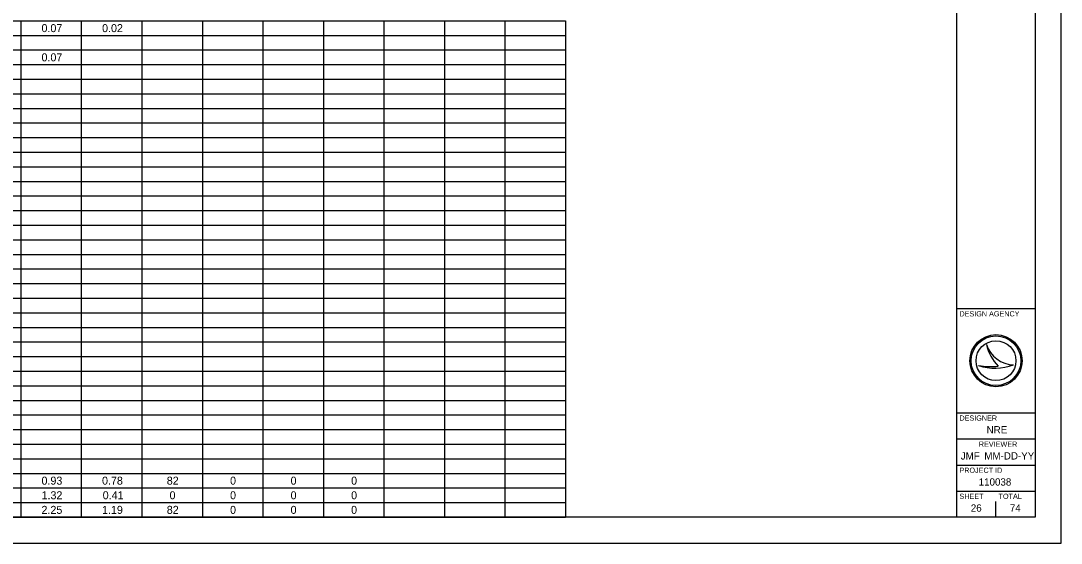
# Model space of a CAD drawing. Extents: x 0 to 34, y 0 to 22.
# Drawn here: x 14.06 to 34, y 0 to 10.02 of the extents above; entities that cross this region are included whole.
import ezdxf

# ---------------------------------------------------------------- set-up
doc = ezdxf.new("R2010")
doc.units = 0
for name, color, linetype in [('SH_Border', 7, 'Continuous'), ('SH_Cut_Line', 7, 'Continuous'), ('SH_Data', 7, 'Continuous'), ('SH_Text', 7, 'Continuous')]:
    doc.layers.add(name, color=color, linetype=linetype)

msp = doc.modelspace()

# ---------------------------------------------------------------- linework, layer by layer
at = {"layer": 'SH_Border'}
for p, q in [((32, 0.5), (32, 21.5)), ((32, 4.5), (33.5, 4.5)), ((32, 2.5), (33.5, 2.5)), ((32, 2), (33.5, 2)), ((32, 1.5), (33.5, 1.5)), ((32, 1), (33.5, 1))]:
    msp.add_line(p, q, dxfattribs=at)
msp.add_lwpolyline([(1.5, 21.5), (33.5, 21.5), (33.5, 0.5), (1.5, 0.5)], close=True, dxfattribs=at)
at = {"layer": 'SH_Cut_Line'}
msp.add_lwpolyline([(0, 0), (34, 0), (34, 22), (0, 22)], close=True, dxfattribs=at)
at = {"layer": 'SH_Data'}
for p, q in [((32.567, 3.81), (32.567, 3.81)), ((32.417, 3.41), (32.417, 3.41)), ((32.75, 3.5), (32.75, 3.5)), ((33.087, 3.419), (33.087, 3.419)), ((32.75, 0.5), (32.75, 0.8)), ((32.375, 0.675), (32.375, 0.675))]:
    msp.add_line(p, q, dxfattribs=at)
for radius in [0.5, 0.477, 0.477, 0.382]:
    msp.add_circle((32.75, 3.5), radius, dxfattribs=at)
for centre, radius, start, end in [((33.116, 3.998), 0.58, 198.9257, 198.9319), ((33.347, 3.97), 0.796, 191.6379, 191.6421), ((33.116, 3.998), 0.58, 198.9319, 267.1657), ((33.347, 3.97), 0.796, 191.6421, 226.0947), ((32.739, 4.37), 1.013, 251.4576, 290.0832), ((32.648, 4.654), 1.266, 259.4964, 259.4995), ((32.739, 4.37), 1.013, 251.4527, 251.4576), ((32.648, 4.654), 1.266, 259.4995, 276.6672)]:
    msp.add_arc(centre, radius, start, end, dxfattribs=at)
at = {"layer": 'SH_Text'}
for p, q in [((3.02, 10.02), (14.06, 10.02)), ((14.06, 10.02), (16.38, 10.02)), ((14.06, 10.02), (14.06, 9.74)), ((15.22, 10.02), (15.22, 9.74)), ((16.38, 10.02), (21.02, 10.02)), ((16.38, 10.02), (16.38, 9.74)), ((17.54, 10.02), (17.54, 9.74)), ((18.7, 10.02), (18.7, 9.74)), ((19.86, 10.02), (19.86, 9.74)), ((21.02, 10.02), (23.34, 10.02)), ((21.02, 10.02), (21.02, 9.74)), ((22.18, 10.02), (22.18, 9.74)), ((23.34, 10.02), (24.5, 10.02)), ((23.34, 10.02), (23.34, 9.74)), ((24.5, 10.02), (24.5, 9.74)), ((3.02, 9.74), (14.06, 9.74)), ((14.06, 9.74), (16.38, 9.74)), ((14.06, 9.74), (14.06, 9.46)), ((15.22, 9.74), (15.22, 9.46)), ((16.38, 9.74), (21.02, 9.74)), ((16.38, 9.74), (16.38, 9.46)), ((17.54, 9.74), (17.54, 9.46)), ((18.7, 9.74), (18.7, 9.46)), ((19.86, 9.74), (19.86, 9.46)), ((21.02, 9.74), (23.34, 9.74)), ((21.02, 9.74), (21.02, 9.46)), ((22.18, 9.74), (22.18, 9.46)), ((23.34, 9.74), (24.5, 9.74)), ((23.34, 9.74), (23.34, 9.46)), ((24.5, 9.74), (24.5, 9.46)), ((3.02, 9.46), (14.06, 9.46)), ((14.06, 9.46), (16.38, 9.46)), ((14.06, 9.46), (14.06, 9.18)), ((15.22, 9.46), (15.22, 9.18)), ((16.38, 9.46), (21.02, 9.46)), ((16.38, 9.46), (16.38, 9.18)), ((17.54, 9.46), (17.54, 9.18)), ((18.7, 9.46), (18.7, 9.18)), ((19.86, 9.46), (19.86, 9.18)), ((21.02, 9.46), (23.34, 9.46)), ((21.02, 9.46), (21.02, 9.18)), ((22.18, 9.46), (22.18, 9.18)), ((23.34, 9.46), (24.5, 9.46)), ((23.34, 9.46), (23.34, 9.18)), ((24.5, 9.46), (24.5, 9.18)), ((3.02, 9.18), (14.06, 9.18)), ((14.06, 9.18), (16.38, 9.18)), ((14.06, 9.18), (14.06, 8.9)), ((15.22, 9.18), (15.22, 8.9)), ((16.38, 9.18), (21.02, 9.18)), ((16.38, 9.18), (16.38, 8.9)), ((17.54, 9.18), (17.54, 8.9)), ((18.7, 9.18), (18.7, 8.9)), ((19.86, 9.18), (19.86, 8.9)), ((21.02, 9.18), (23.34, 9.18)), ((21.02, 9.18), (21.02, 8.9)), ((22.18, 9.18), (22.18, 8.9)), ((23.34, 9.18), (24.5, 9.18)), ((23.34, 9.18), (23.34, 8.9)), ((24.5, 9.18), (24.5, 8.9)), ((3.02, 8.9), (14.06, 8.9)), ((14.06, 8.9), (16.38, 8.9)), ((14.06, 8.9), (14.06, 8.62)), ((15.22, 8.9), (15.22, 8.62)), ((16.38, 8.9), (21.02, 8.9)), ((16.38, 8.9), (16.38, 8.62)), ((17.54, 8.9), (17.54, 8.62)), ((18.7, 8.9), (18.7, 8.62)), ((19.86, 8.9), (19.86, 8.62)), ((21.02, 8.9), (23.34, 8.9)), ((21.02, 8.9), (21.02, 8.62)), ((22.18, 8.9), (22.18, 8.62)), ((23.34, 8.9), (24.5, 8.9)), ((23.34, 8.9), (23.34, 8.62)), ((24.5, 8.9), (24.5, 8.62)), ((3.02, 8.62), (14.06, 8.62)), ((14.06, 8.62), (16.38, 8.62)), ((14.06, 8.62), (14.06, 8.34)), ((15.22, 8.62), (15.22, 8.34)), ((16.38, 8.62), (21.02, 8.62)), ((16.38, 8.62), (16.38, 8.34)), ((17.54, 8.62), (17.54, 8.34)), ((18.7, 8.62), (18.7, 8.34)), ((19.86, 8.62), (19.86, 8.34)), ((21.02, 8.62), (23.34, 8.62)), ((21.02, 8.62), (21.02, 8.34)), ((22.18, 8.62), (22.18, 8.34)), ((23.34, 8.62), (24.5, 8.62)), ((23.34, 8.62), (23.34, 8.34)), ((24.5, 8.62), (24.5, 8.34)), ((3.02, 8.34), (14.06, 8.34)), ((14.06, 8.34), (16.38, 8.34)), ((14.06, 8.34), (14.06, 8.06)), ((15.22, 8.34), (15.22, 8.06)), ((16.38, 8.34), (21.02, 8.34)), ((16.38, 8.34), (16.38, 8.06)), ((17.54, 8.34), (17.54, 8.06)), ((18.7, 8.34), (18.7, 8.06)), ((19.86, 8.34), (19.86, 8.06)), ((21.02, 8.34), (23.34, 8.34)), ((21.02, 8.34), (21.02, 8.06)), ((22.18, 8.34), (22.18, 8.06)), ((23.34, 8.34), (24.5, 8.34)), ((23.34, 8.34), (23.34, 8.06)), ((24.5, 8.34), (24.5, 8.06)), ((3.02, 8.06), (14.06, 8.06)), ((14.06, 8.06), (16.38, 8.06)), ((14.06, 8.06), (14.06, 7.78)), ((15.22, 8.06), (15.22, 7.78)), ((16.38, 8.06), (21.02, 8.06)), ((16.38, 8.06), (16.38, 7.78)), ((17.54, 8.06), (17.54, 7.78)), ((18.7, 8.06), (18.7, 7.78)), ((19.86, 8.06), (19.86, 7.78)), ((21.02, 8.06), (23.34, 8.06)), ((21.02, 8.06), (21.02, 7.78)), ((22.18, 8.06), (22.18, 7.78)), ((23.34, 8.06), (24.5, 8.06)), ((23.34, 8.06), (23.34, 7.78)), ((24.5, 8.06), (24.5, 7.78)), ((3.02, 7.78), (14.06, 7.78)), ((14.06, 7.78), (16.38, 7.78)), ((14.06, 7.78), (14.06, 7.5)), ((15.22, 7.78), (15.22, 7.5)), ((16.38, 7.78), (21.02, 7.78)), ((16.38, 7.78), (16.38, 7.5)), ((17.54, 7.78), (17.54, 7.5)), ((18.7, 7.78), (18.7, 7.5)), ((19.86, 7.78), (19.86, 7.5)), ((21.02, 7.78), (23.34, 7.78)), ((21.02, 7.78), (21.02, 7.5)), ((22.18, 7.78), (22.18, 7.5)), ((23.34, 7.78), (24.5, 7.78)), ((23.34, 7.78), (23.34, 7.5)), ((24.5, 7.78), (24.5, 7.5)), ((3.02, 7.5), (14.06, 7.5)), ((14.06, 7.5), (16.38, 7.5)), ((14.06, 7.5), (14.06, 7.22)), ((15.22, 7.5), (15.22, 7.22)), ((16.38, 7.5), (21.02, 7.5)), ((16.38, 7.5), (16.38, 7.22)), ((17.54, 7.5), (17.54, 7.22)), ((18.7, 7.5), (18.7, 7.22)), ((19.86, 7.5), (19.86, 7.22)), ((21.02, 7.5), (23.34, 7.5)), ((21.02, 7.5), (21.02, 7.22)), ((22.18, 7.5), (22.18, 7.22)), ((23.34, 7.5), (24.5, 7.5)), ((23.34, 7.5), (23.34, 7.22)), ((24.5, 7.5), (24.5, 7.22)), ((3.02, 7.22), (14.06, 7.22)), ((14.06, 7.22), (16.38, 7.22)), ((14.06, 7.22), (14.06, 6.94)), ((15.22, 7.22), (15.22, 6.94)), ((16.38, 7.22), (21.02, 7.22)), ((16.38, 7.22), (16.38, 6.94)), ((17.54, 7.22), (17.54, 6.94)), ((18.7, 7.22), (18.7, 6.94)), ((19.86, 7.22), (19.86, 6.94)), ((21.02, 7.22), (23.34, 7.22)), ((21.02, 7.22), (21.02, 6.94)), ((22.18, 7.22), (22.18, 6.94)), ((23.34, 7.22), (24.5, 7.22)), ((23.34, 7.22), (23.34, 6.94)), ((24.5, 7.22), (24.5, 6.94)), ((3.02, 6.94), (14.06, 6.94)), ((14.06, 6.94), (16.38, 6.94)), ((14.06, 6.94), (14.06, 6.66)), ((15.22, 6.94), (15.22, 6.66)), ((16.38, 6.94), (21.02, 6.94)), ((16.38, 6.94), (16.38, 6.66)), ((17.54, 6.94), (17.54, 6.66)), ((18.7, 6.94), (18.7, 6.66)), ((19.86, 6.94), (19.86, 6.66)), ((21.02, 6.94), (23.34, 6.94)), ((21.02, 6.94), (21.02, 6.66)), ((22.18, 6.94), (22.18, 6.66)), ((23.34, 6.94), (24.5, 6.94)), ((23.34, 6.94), (23.34, 6.66)), ((24.5, 6.94), (24.5, 6.66)), ((3.02, 6.66), (14.06, 6.66)), ((14.06, 6.66), (16.38, 6.66)), ((14.06, 6.66), (14.06, 6.38)), ((15.22, 6.66), (15.22, 6.38)), ((16.38, 6.66), (21.02, 6.66)), ((16.38, 6.66), (16.38, 6.38)), ((17.54, 6.66), (17.54, 6.38)), ((18.7, 6.66), (18.7, 6.38)), ((19.86, 6.66), (19.86, 6.38)), ((21.02, 6.66), (23.34, 6.66)), ((21.02, 6.66), (21.02, 6.38)), ((22.18, 6.66), (22.18, 6.38)), ((23.34, 6.66), (24.5, 6.66)), ((23.34, 6.66), (23.34, 6.38)), ((24.5, 6.66), (24.5, 6.38)), ((3.02, 6.38), (14.06, 6.38)), ((14.06, 6.38), (16.38, 6.38)), ((14.06, 6.38), (14.06, 6.1)), ((15.22, 6.38), (15.22, 6.1)), ((16.38, 6.38), (21.02, 6.38)), ((16.38, 6.38), (16.38, 6.1)), ((17.54, 6.38), (17.54, 6.1)), ((18.7, 6.38), (18.7, 6.1)), ((19.86, 6.38), (19.86, 6.1)), ((21.02, 6.38), (23.34, 6.38)), ((21.02, 6.38), (21.02, 6.1)), ((22.18, 6.38), (22.18, 6.1)), ((23.34, 6.38), (24.5, 6.38)), ((23.34, 6.38), (23.34, 6.1)), ((24.5, 6.38), (24.5, 6.1)), ((3.02, 6.1), (14.06, 6.1)), ((14.06, 6.1), (16.38, 6.1)), ((14.06, 6.1), (14.06, 5.82)), ((15.22, 6.1), (15.22, 5.82)), ((16.38, 6.1), (21.02, 6.1)), ((16.38, 6.1), (16.38, 5.82)), ((17.54, 6.1), (17.54, 5.82)), ((18.7, 6.1), (18.7, 5.82)), ((19.86, 6.1), (19.86, 5.82)), ((21.02, 6.1), (23.34, 6.1)), ((21.02, 6.1), (21.02, 5.82)), ((22.18, 6.1), (22.18, 5.82)), ((23.34, 6.1), (24.5, 6.1)), ((23.34, 6.1), (23.34, 5.82)), ((24.5, 6.1), (24.5, 5.82)), ((3.02, 5.82), (14.06, 5.82)), ((14.06, 5.82), (16.38, 5.82)), ((14.06, 5.82), (14.06, 5.54)), ((15.22, 5.82), (15.22, 5.54)), ((16.38, 5.82), (21.02, 5.82)), ((16.38, 5.82), (16.38, 5.54)), ((17.54, 5.82), (17.54, 5.54)), ((18.7, 5.82), (18.7, 5.54)), ((19.86, 5.82), (19.86, 5.54)), ((21.02, 5.82), (23.34, 5.82)), ((21.02, 5.82), (21.02, 5.54)), ((22.18, 5.82), (22.18, 5.54)), ((23.34, 5.82), (24.5, 5.82)), ((23.34, 5.82), (23.34, 5.54)), ((24.5, 5.82), (24.5, 5.54)), ((3.02, 5.54), (14.06, 5.54)), ((14.06, 5.54), (16.38, 5.54)), ((14.06, 5.54), (14.06, 4.98)), ((15.22, 5.54), (15.22, 4.98)), ((16.38, 5.54), (21.02, 5.54)), ((16.38, 5.54), (16.38, 4.98)), ((17.54, 5.54), (17.54, 4.98)), ((18.7, 5.54), (18.7, 4.98)), ((19.86, 5.54), (19.86, 4.98)), ((21.02, 5.54), (23.34, 5.54)), ((21.02, 5.54), (21.02, 4.98)), ((22.18, 5.54), (22.18, 4.98)), ((23.34, 5.54), (24.5, 5.54)), ((23.34, 5.54), (23.34, 4.98)), ((24.5, 5.54), (24.5, 4.98)), ((3.02, 5.26), (14.06, 5.26)), ((14.06, 5.26), (16.38, 5.26)), ((16.38, 5.26), (21.02, 5.26)), ((21.02, 5.26), (23.34, 5.26)), ((23.34, 5.26), (24.5, 5.26)), ((3.02, 4.98), (14.06, 4.98)), ((14.06, 4.98), (16.38, 4.98)), ((14.06, 4.98), (14.06, 4.7)), ((15.22, 4.98), (15.22, 4.7)), ((16.38, 4.98), (21.02, 4.98)), ((16.38, 4.98), (16.38, 4.7)), ((17.54, 4.98), (17.54, 4.7)), ((18.7, 4.98), (18.7, 4.7)), ((19.86, 4.98), (19.86, 4.7)), ((21.02, 4.98), (23.34, 4.98)), ((21.02, 4.98), (21.02, 4.7)), ((22.18, 4.98), (22.18, 4.7)), ((23.34, 4.98), (24.5, 4.98)), ((23.34, 4.98), (23.34, 4.7)), ((24.5, 4.98), (24.5, 4.7)), ((3.02, 4.7), (14.06, 4.7)), ((14.06, 4.7), (16.38, 4.7)), ((14.06, 4.7), (14.06, 4.42)), ((15.22, 4.7), (15.22, 4.42)), ((16.38, 4.7), (21.02, 4.7)), ((16.38, 4.7), (16.38, 4.42)), ((17.54, 4.7), (17.54, 4.42)), ((18.7, 4.7), (18.7, 4.42)), ((19.86, 4.7), (19.86, 4.42)), ((21.02, 4.7), (23.34, 4.7)), ((21.02, 4.7), (21.02, 4.42)), ((22.18, 4.7), (22.18, 4.42)), ((23.34, 4.7), (24.5, 4.7)), ((23.34, 4.7), (23.34, 4.42)), ((24.5, 4.7), (24.5, 4.42)), ((3.02, 4.42), (14.06, 4.42)), ((14.06, 4.42), (16.38, 4.42)), ((14.06, 4.42), (14.06, 4.14)), ((15.22, 4.42), (15.22, 4.14)), ((16.38, 4.42), (21.02, 4.42)), ((16.38, 4.42), (16.38, 4.14)), ((17.54, 4.42), (17.54, 4.14)), ((18.7, 4.42), (18.7, 4.14)), ((19.86, 4.42), (19.86, 4.14)), ((21.02, 4.42), (23.34, 4.42)), ((21.02, 4.42), (21.02, 4.14)), ((22.18, 4.42), (22.18, 4.14)), ((23.34, 4.42), (24.5, 4.42)), ((23.34, 4.42), (23.34, 4.14)), ((24.5, 4.42), (24.5, 4.14)), ((3.02, 4.14), (14.06, 4.14)), ((14.06, 4.14), (16.38, 4.14)), ((14.06, 4.14), (14.06, 3.58)), ((15.22, 4.14), (15.22, 3.58)), ((16.38, 4.14), (21.02, 4.14)), ((16.38, 4.14), (16.38, 3.58)), ((17.54, 4.14), (17.54, 3.58)), ((18.7, 4.14), (18.7, 3.58)), ((19.86, 4.14), (19.86, 3.58)), ((21.02, 4.14), (23.34, 4.14)), ((21.02, 4.14), (21.02, 3.58)), ((22.18, 4.14), (22.18, 3.58)), ((23.34, 4.14), (24.5, 4.14)), ((23.34, 4.14), (23.34, 3.58)), ((24.5, 4.14), (24.5, 3.58)), ((3.02, 3.86), (14.06, 3.86)), ((14.06, 3.86), (16.38, 3.86)), ((16.38, 3.86), (21.02, 3.86)), ((21.02, 3.86), (23.34, 3.86)), ((23.34, 3.86), (24.5, 3.86)), ((3.02, 3.58), (14.06, 3.58)), ((14.06, 3.58), (16.38, 3.58)), ((14.06, 3.58), (14.06, 3.3)), ((15.22, 3.58), (15.22, 3.3)), ((16.38, 3.58), (21.02, 3.58)), ((16.38, 3.58), (16.38, 3.3)), ((17.54, 3.58), (17.54, 3.3)), ((18.7, 3.58), (18.7, 3.3)), ((19.86, 3.58), (19.86, 3.3)), ((21.02, 3.58), (23.34, 3.58)), ((21.02, 3.58), (21.02, 3.3)), ((22.18, 3.58), (22.18, 3.3)), ((23.34, 3.58), (24.5, 3.58)), ((23.34, 3.58), (23.34, 3.3)), ((24.5, 3.58), (24.5, 3.3)), ((3.02, 3.3), (14.06, 3.3)), ((14.06, 3.3), (16.38, 3.3)), ((14.06, 3.3), (14.06, 3.02)), ((15.22, 3.3), (15.22, 3.02)), ((16.38, 3.3), (21.02, 3.3)), ((16.38, 3.3), (16.38, 3.02)), ((17.54, 3.3), (17.54, 3.02)), ((18.7, 3.3), (18.7, 3.02)), ((19.86, 3.3), (19.86, 3.02)), ((21.02, 3.3), (23.34, 3.3)), ((21.02, 3.3), (21.02, 3.02)), ((22.18, 3.3), (22.18, 3.02)), ((23.34, 3.3), (24.5, 3.3)), ((23.34, 3.3), (23.34, 3.02)), ((24.5, 3.3), (24.5, 3.02)), ((3.02, 3.02), (14.06, 3.02)), ((14.06, 3.02), (16.38, 3.02)), ((14.06, 3.02), (14.06, 2.74)), ((15.22, 3.02), (15.22, 2.74)), ((16.38, 3.02), (21.02, 3.02)), ((16.38, 3.02), (16.38, 2.74)), ((17.54, 3.02), (17.54, 2.74)), ((18.7, 3.02), (18.7, 2.74)), ((19.86, 3.02), (19.86, 2.74)), ((21.02, 3.02), (23.34, 3.02)), ((21.02, 3.02), (21.02, 2.74)), ((22.18, 3.02), (22.18, 2.74)), ((23.34, 3.02), (24.5, 3.02)), ((23.34, 3.02), (23.34, 2.74)), ((24.5, 3.02), (24.5, 2.74)), ((3.02, 2.74), (14.06, 2.74)), ((14.06, 2.74), (16.38, 2.74)), ((14.06, 2.74), (14.06, 2.18)), ((15.22, 2.74), (15.22, 2.18)), ((16.38, 2.74), (21.02, 2.74)), ((16.38, 2.74), (16.38, 2.18)), ((17.54, 2.74), (17.54, 2.18)), ((18.7, 2.74), (18.7, 2.18)), ((19.86, 2.74), (19.86, 2.18)), ((21.02, 2.74), (23.34, 2.74)), ((21.02, 2.74), (21.02, 2.18)), ((22.18, 2.74), (22.18, 2.18)), ((23.34, 2.74), (24.5, 2.74)), ((23.34, 2.74), (23.34, 2.18)), ((24.5, 2.74), (24.5, 2.18)), ((3.02, 2.46), (14.06, 2.46)), ((14.06, 2.46), (16.38, 2.46)), ((16.38, 2.46), (21.02, 2.46)), ((21.02, 2.46), (23.34, 2.46)), ((23.34, 2.46), (24.5, 2.46)), ((3.02, 2.18), (14.06, 2.18)), ((14.06, 2.18), (16.38, 2.18)), ((14.06, 2.18), (14.06, 1.9)), ((15.22, 2.18), (15.22, 1.9)), ((16.38, 2.18), (21.02, 2.18)), ((16.38, 2.18), (16.38, 1.9)), ((17.54, 2.18), (17.54, 1.9)), ((18.7, 2.18), (18.7, 1.9)), ((19.86, 2.18), (19.86, 1.9)), ((21.02, 2.18), (23.34, 2.18)), ((21.02, 2.18), (21.02, 1.9)), ((22.18, 2.18), (22.18, 1.9)), ((23.34, 2.18), (24.5, 2.18)), ((23.34, 2.18), (23.34, 1.9)), ((24.5, 2.18), (24.5, 1.9)), ((3.02, 1.9), (14.06, 1.9)), ((14.06, 1.9), (16.38, 1.9)), ((14.06, 1.9), (14.06, 1.62)), ((15.22, 1.9), (15.22, 1.62)), ((16.38, 1.9), (21.02, 1.9)), ((16.38, 1.9), (16.38, 1.62)), ((17.54, 1.9), (17.54, 1.62)), ((18.7, 1.9), (18.7, 1.62)), ((19.86, 1.9), (19.86, 1.62)), ((21.02, 1.9), (23.34, 1.9)), ((21.02, 1.9), (21.02, 1.62)), ((22.18, 1.9), (22.18, 1.62)), ((23.34, 1.9), (24.5, 1.9)), ((23.34, 1.9), (23.34, 1.62)), ((24.5, 1.9), (24.5, 1.62)), ((3.02, 1.62), (14.06, 1.62)), ((14.06, 1.62), (16.38, 1.62)), ((14.06, 1.62), (14.06, 1.34)), ((15.22, 1.62), (15.22, 1.34)), ((16.38, 1.62), (21.02, 1.62)), ((16.38, 1.62), (16.38, 1.34)), ((17.54, 1.62), (17.54, 1.34)), ((18.7, 1.62), (18.7, 1.34)), ((19.86, 1.62), (19.86, 1.34)), ((21.02, 1.62), (23.34, 1.62)), ((21.02, 1.62), (21.02, 1.34)), ((22.18, 1.62), (22.18, 1.34)), ((23.34, 1.62), (24.5, 1.62)), ((23.34, 1.62), (23.34, 1.34)), ((24.5, 1.62), (24.5, 1.34)), ((3.02, 1.34), (14.06, 1.34)), ((14.06, 1.34), (16.38, 1.34)), ((14.06, 1.34), (14.06, 0.78)), ((15.22, 1.34), (15.22, 0.78)), ((16.38, 1.34), (21.02, 1.34)), ((16.38, 1.34), (16.38, 0.78)), ((17.54, 1.34), (17.54, 0.78)), ((18.7, 1.34), (18.7, 0.78)), ((19.86, 1.34), (19.86, 0.78)), ((21.02, 1.34), (23.34, 1.34)), ((21.02, 1.34), (21.02, 0.78)), ((22.18, 1.34), (22.18, 0.78)), ((23.34, 1.34), (24.5, 1.34)), ((23.34, 1.34), (23.34, 0.78)), ((24.5, 1.34), (24.5, 0.78)), ((3.02, 1.06), (14.06, 1.06)), ((14.06, 1.06), (16.38, 1.06)), ((16.38, 1.06), (21.02, 1.06)), ((21.02, 1.06), (23.34, 1.06)), ((23.34, 1.06), (24.5, 1.06)), ((3.02, 0.78), (14.06, 0.78)), ((14.06, 0.78), (16.38, 0.78)), ((14.06, 0.78), (14.06, 0.5)), ((15.22, 0.78), (15.22, 0.5)), ((16.38, 0.78), (21.02, 0.78)), ((16.38, 0.78), (16.38, 0.5)), ((17.54, 0.78), (17.54, 0.5)), ((18.7, 0.78), (18.7, 0.5)), ((19.86, 0.78), (19.86, 0.5)), ((21.02, 0.78), (23.34, 0.78)), ((21.02, 0.78), (21.02, 0.5)), ((22.18, 0.78), (22.18, 0.5)), ((23.34, 0.78), (24.5, 0.78)), ((23.34, 0.78), (23.34, 0.5)), ((24.5, 0.78), (24.5, 0.5)), ((3.02, 0.5), (14.06, 0.5)), ((14.06, 0.5), (16.38, 0.5)), ((16.38, 0.5), (21.02, 0.5)), ((21.02, 0.5), (23.34, 0.5)), ((23.34, 0.5), (24.5, 0.5))]:
    msp.add_line(p, q, dxfattribs=at)

# ---------------------------------------------------------------- texts
at = {"layer": 'SH_Data'}
for s, height, p in [('DESIGN AGENCY', 0.1, (32.05, 4.35)), ('DESIGNER', 0.1, (32.05, 2.35)), ('NRE', 0.14, (32.571, 2.105)), ('REVIEWER', 0.1, (32.422, 1.85)), ('JMF', 0.14, (32.075, 1.605)), ('MM-DD-YY', 0.14, (32.527, 1.605)), ('PROJECT ID', 0.1, (32.05, 1.35)), ('110038', 0.14, (32.419, 1.105)), ('SHEET', 0.1, (32.05, 0.85)), ('TOTAL', 0.1, (32.8, 0.85)), ('26', 0.14, (32.268, 0.605)), ('74', 0.14, (33.016, 0.605))]:
    msp.add_text(s, height=height, dxfattribs=at).set_placement(p)
at = {"layer": 'SH_Text'}
for s, height, p in [('0.07', 0.1533, (14.457, 9.803)), ('0.02', 0.1533, (15.618, 9.803)), ('0.07', 0.1533, (14.457, 9.243)), ('0.93', 0.1533, (14.457, 1.123)), ('0.78', 0.1533, (15.617, 1.123)), ('82', 0.1533, (16.858, 1.123)), ('0', 0.153, (18.071, 1.123)), ('0', 0.153, (19.231, 1.123)), ('0', 0.153, (20.391, 1.123)), ('1.32', 0.1533, (14.458, 0.843)), ('0.41', 0.1533, (15.63, 0.843)), ('0', 0.153, (16.911, 0.843)), ('0', 0.153, (18.071, 0.843)), ('0', 0.153, (19.231, 0.843)), ('0', 0.153, (20.391, 0.843)), ('2.25', 0.1533, (14.457, 0.563)), ('1.19', 0.1533, (15.617, 0.563)), ('82', 0.1533, (16.858, 0.563)), ('0', 0.153, (18.071, 0.563)), ('0', 0.153, (19.231, 0.563)), ('0', 0.153, (20.391, 0.563))]:
    msp.add_text(s, height=height, dxfattribs=at).set_placement(p)

doc.saveas('drawing.dxf')
